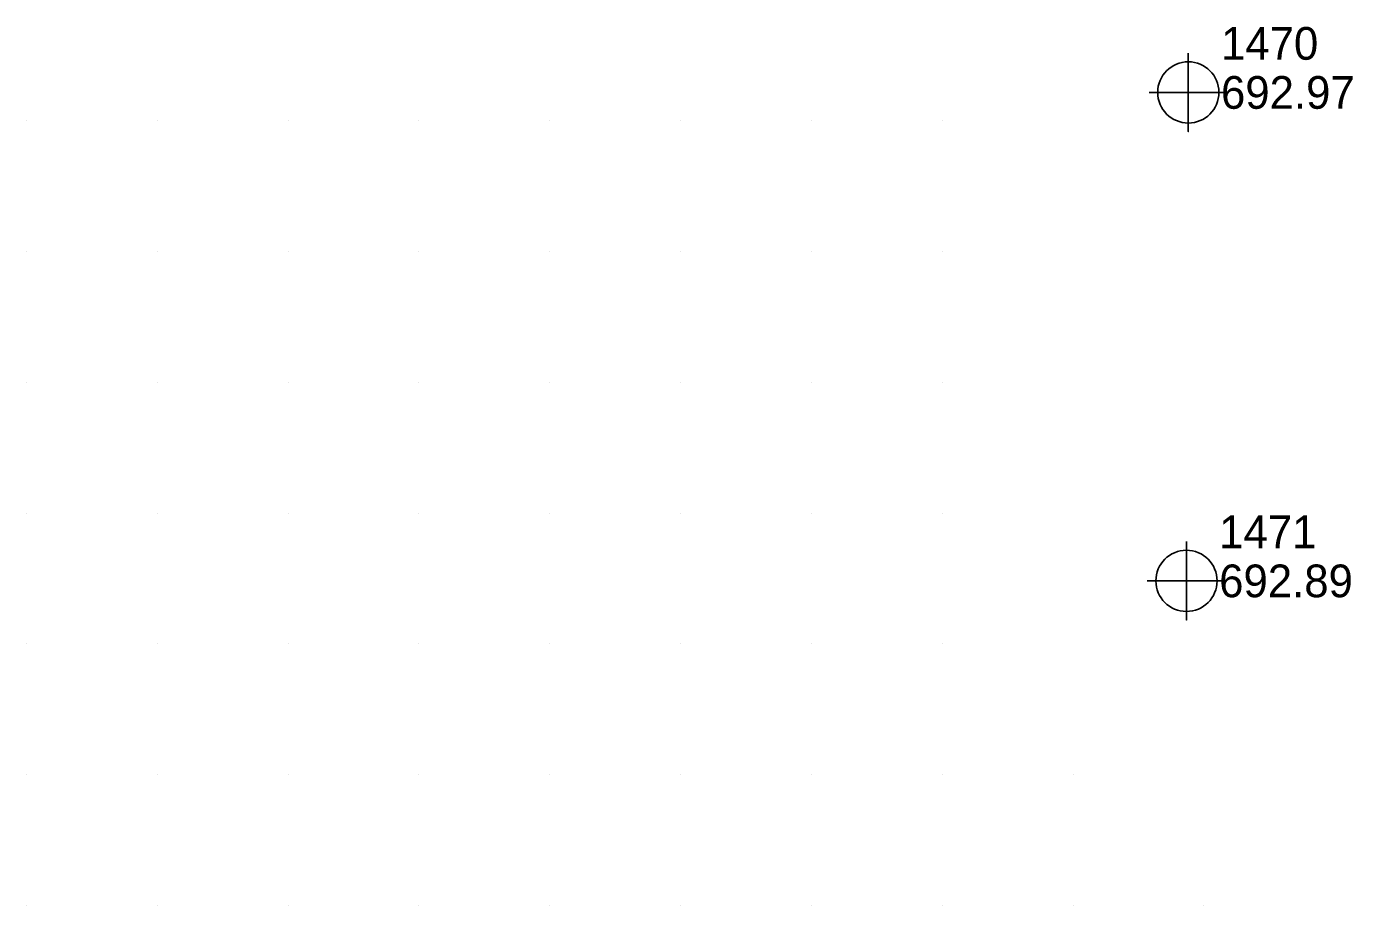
# Model space of a CAD drawing. Extents: x 1755643 to 1760494, y 736519 to 737621.
# Drawn here: x 1757765.4 to 1757866.7, y 737045 to 737112.2 of the extents above; entities that cross this region are included whole.
import ezdxf

# ---------------------------------------------------------------- set-up
doc = ezdxf.new("R2010")
doc.units = 0
for name, color, linetype in [('Exist Horizontal Alignment Curve and Spiral Data', 7, 'Continuous'), ('Exist Roads EOT', 7, 'Continuous'), ('Prop Paint Stripe', 7, 'Continuous'), ('Prop Paved Shoulder', 7, 'Continuous')]:
    doc.layers.add(name, color=color, linetype=linetype)

msp = doc.modelspace()

# ---------------------------------------------------------------- linework, layer by layer
at = {"layer": 'Exist Horizontal Alignment Curve and Spiral Data'}
for points in [[(1757854.19, 737110.16), (1757854.19, 737104.16), (1757854.19, 737107.16), (1757857.19, 737107.16), (1757851.19, 737107.16)], [(1757854.05, 737072.81), (1757854.05, 737066.81), (1757854.05, 737069.81), (1757857.05, 737069.81), (1757851.05, 737069.81)]]:
    msp.add_lwpolyline(points, dxfattribs=at)
for centre in [(1757854.19, 737107.16), (1757854.05, 737069.81)]:
    msp.add_circle(centre, 2.34, dxfattribs=at)
at = {"layer": 'Prop Paint Stripe'}
for p, q in [((1757765.37, 737105), (1757765.37, 737105)), ((1757775.37, 737105), (1757775.37, 737105)), ((1757785.37, 737105), (1757785.37, 737105)), ((1757795.37, 737105), (1757795.37, 737105)), ((1757805.37, 737105), (1757805.37, 737105)), ((1757815.37, 737105), (1757815.37, 737105)), ((1757825.37, 737105), (1757825.37, 737105)), ((1757835.37, 737105), (1757835.37, 737105)), ((1757765.37, 737094.99), (1757765.37, 737094.99)), ((1757775.37, 737094.99), (1757775.37, 737094.99)), ((1757785.37, 737094.99), (1757785.37, 737094.99)), ((1757795.37, 737094.99), (1757795.37, 737094.99)), ((1757805.37, 737094.99), (1757805.37, 737094.99)), ((1757815.37, 737094.99), (1757815.37, 737094.99)), ((1757825.37, 737094.99), (1757825.37, 737094.99)), ((1757835.37, 737094.99), (1757835.37, 737094.99)), ((1757765.37, 737084.99), (1757765.37, 737084.99)), ((1757775.37, 737084.99), (1757775.37, 737084.99)), ((1757785.37, 737084.99), (1757785.37, 737084.99)), ((1757795.37, 737084.99), (1757795.37, 737084.99)), ((1757805.37, 737084.99), (1757805.37, 737084.99)), ((1757815.37, 737084.99), (1757815.37, 737084.99)), ((1757825.37, 737084.99), (1757825.37, 737084.99)), ((1757835.37, 737084.99), (1757835.37, 737084.99)), ((1757765.37, 737074.99), (1757765.37, 737074.99)), ((1757775.37, 737074.99), (1757775.37, 737074.99)), ((1757785.37, 737074.99), (1757785.37, 737074.99)), ((1757795.37, 737074.99), (1757795.37, 737074.99)), ((1757805.37, 737074.99), (1757805.37, 737074.99)), ((1757815.37, 737074.99), (1757815.37, 737074.99)), ((1757825.37, 737074.99), (1757825.37, 737074.99)), ((1757835.37, 737074.99), (1757835.37, 737074.99)), ((1757765.37, 737064.99), (1757765.37, 737064.99)), ((1757775.37, 737064.99), (1757775.37, 737064.99)), ((1757785.37, 737064.99), (1757785.37, 737064.99)), ((1757795.37, 737064.99), (1757795.37, 737064.99)), ((1757805.37, 737064.99), (1757805.37, 737064.99)), ((1757815.37, 737064.99), (1757815.37, 737064.99)), ((1757825.37, 737064.99), (1757825.37, 737064.99)), ((1757835.37, 737064.99), (1757835.37, 737064.99)), ((1757765.37, 737054.99), (1757765.37, 737054.99)), ((1757775.37, 737054.99), (1757775.37, 737054.99)), ((1757785.37, 737054.99), (1757785.37, 737054.99)), ((1757795.37, 737054.99), (1757795.37, 737054.99)), ((1757805.37, 737054.99), (1757805.37, 737054.99)), ((1757815.37, 737054.99), (1757815.37, 737054.99)), ((1757825.37, 737054.99), (1757825.37, 737054.99)), ((1757835.37, 737054.99), (1757835.37, 737054.99)), ((1757845.38, 737054.99), (1757845.38, 737054.99)), ((1757765.37, 737044.99), (1757765.37, 737044.99)), ((1757775.37, 737044.99), (1757775.37, 737044.99)), ((1757785.37, 737044.99), (1757785.37, 737044.99)), ((1757795.37, 737044.99), (1757795.37, 737044.99)), ((1757805.37, 737044.99), (1757805.37, 737044.99)), ((1757815.37, 737044.99), (1757815.37, 737044.99)), ((1757825.37, 737044.99), (1757825.37, 737044.99)), ((1757835.37, 737044.99), (1757835.37, 737044.99)), ((1757845.38, 737044.99), (1757845.38, 737044.99)), ((1757855.38, 737044.99), (1757855.38, 737044.99))]:
    msp.add_line(p, q, dxfattribs=at)

# ---------------------------------------------------------------- texts
at = {"layer": 'Exist Roads EOT'}
for s, p in [('1470', (1757856.69, 737109.66)), ('1471', (1757856.55, 737072.31))]:
    msp.add_text(s, height=2.5, dxfattribs=at).set_placement(p)
at = {"layer": 'Prop Paved Shoulder'}
for s, p in [('692.97', (1757856.69, 737105.91)), ('692.89', (1757856.55, 737068.56))]:
    msp.add_text(s, height=2.5, dxfattribs=at).set_placement(p)

doc.saveas('drawing.dxf')
